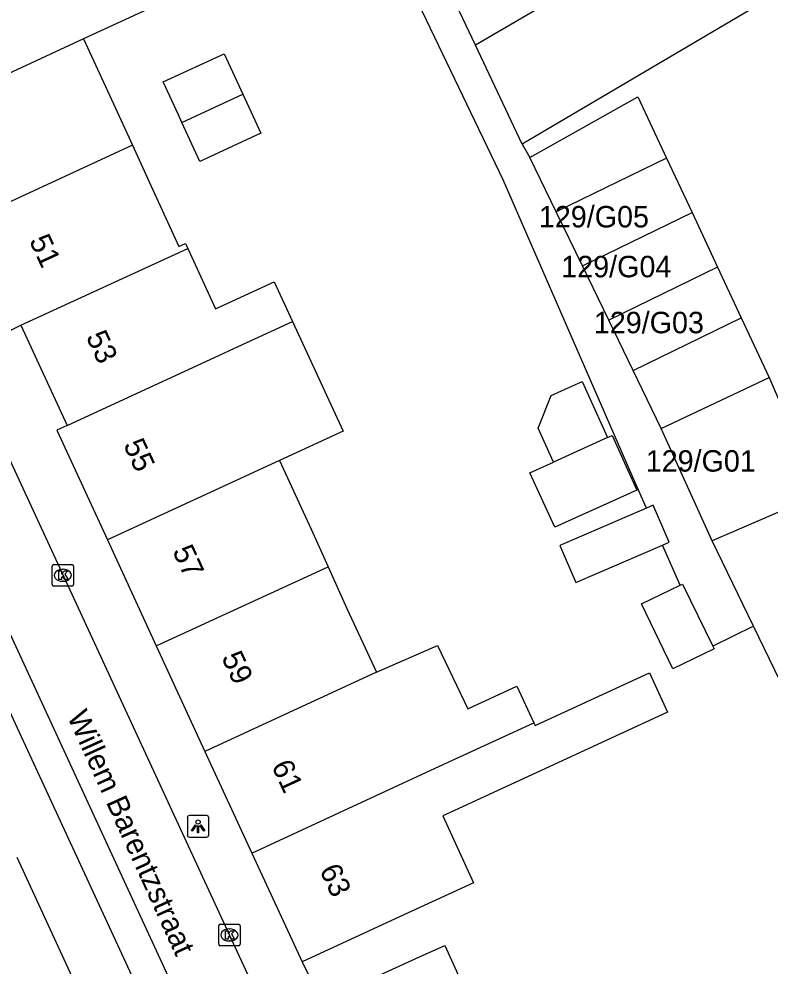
# Model space of a CAD drawing. Extents: x 160379 to 161131, y 383940 to 384849.
# Drawn here: x 161005.91 to 161040.91, y 384363.89 to 384408.04 of the extents above; entities that cross this region are included whole.
import ezdxf

# ---------------------------------------------------------------- set-up
doc = ezdxf.new("R2010")
doc.units = 0
for name, color, linetype in [('IMGEO_Kolk', 7, 'Continuous'), ('IMGEO_Lichtpunt', 7, 'Continuous'), ('IMGEO_Openbare_ruimte_label', 7, 'Continuous'), ('IMGEO_Pand', 7, 'Continuous'), ('IMGEO_Pand_nummerreeks', 7, 'Continuous'), ('IMGEO_Rijbaan_lokaal_open', 7, 'Continuous'), ('IMGEO_Voetpad_open', 7, 'Continuous')]:
    doc.layers.add(name, color=color, linetype=linetype)

msp = doc.modelspace()

# ---------------------------------------------------------------- linework, layer by layer
at = {"layer": 'IMGEO_Kolk'}
for p, q in [((161007.453, 384381.681), (161007.453, 384382.533)), ((161007.528, 384382.607), (161008.38, 384382.607)), ((161008.454, 384382.533), (161008.454, 384381.681)), ((161007.941, 384382.387), (161007.966, 384382.387)), ((161008.38, 384381.607), (161007.528, 384381.607)), ((161007.964, 384381.827), (161007.939, 384381.827)), ((161015.217, 384364.916), (161015.217, 384365.768)), ((161015.292, 384365.842), (161016.144, 384365.842)), ((161016.218, 384365.768), (161016.218, 384364.916)), ((161015.705, 384365.622), (161015.73, 384365.622)), ((161016.144, 384364.842), (161015.292, 384364.842)), ((161015.728, 384365.062), (161015.703, 384365.062))]:
    msp.add_line(p, q, dxfattribs=at)
for points in [[(161007.453, 384381.681), (161007.453, 384382.533)], [(161007.528, 384382.607), (161008.38, 384382.607)], [(161008.454, 384382.533), (161008.454, 384381.681)], [(161007.774, 384382.307), (161007.897, 384382.307), (161007.897, 384382.156), (161008.027, 384382.307), (161008.191, 384382.307), (161008.045, 384382.156), (161008.198, 384381.907), (161008.046, 384381.907), (161007.961, 384382.071), (161007.897, 384382.004), (161007.897, 384381.907), (161007.774, 384381.907), (161007.774, 384382.307)], [(161008.38, 384381.607), (161007.528, 384381.607)], [(161015.217, 384364.916), (161015.217, 384365.768)], [(161015.292, 384365.842), (161016.144, 384365.842)], [(161016.218, 384365.768), (161016.218, 384364.916)], [(161015.538, 384365.542), (161015.661, 384365.542), (161015.661, 384365.391), (161015.791, 384365.542), (161015.955, 384365.542), (161015.809, 384365.391), (161015.962, 384365.142), (161015.81, 384365.142), (161015.725, 384365.306), (161015.661, 384365.239), (161015.661, 384365.142), (161015.538, 384365.142), (161015.538, 384365.542)], [(161016.144, 384364.842), (161015.292, 384364.842)]]:
    msp.add_lwpolyline(points, dxfattribs=at)
for centre, start, end in [((161007.53, 384382.531), 91.552, 178.448), ((161007.53, 384382.531), 91.552, 178.448), ((161008.378, 384382.531), 1.552, 88.448), ((161008.378, 384382.531), 1.552, 88.448), ((161007.53, 384381.683), 181.552, 268.448), ((161007.53, 384381.683), 181.552, 268.448), ((161008.378, 384381.683), 271.552, 358.448), ((161008.378, 384381.683), 271.552, 358.448), ((161015.294, 384365.766), 91.552, 178.448), ((161015.294, 384365.766), 91.552, 178.448), ((161016.142, 384365.766), 1.552, 88.448), ((161016.142, 384365.766), 1.552, 88.448), ((161015.294, 384364.918), 181.552, 268.448), ((161015.294, 384364.918), 181.552, 268.448), ((161016.142, 384364.918), 271.552, 358.448), ((161016.142, 384364.918), 271.552, 358.448)]:
    msp.add_arc(centre, 0.0765, start, end, dxfattribs=at)
for centre, major_axis, ratio, start_param, end_param in [((161007.94, 384382.107), (-0.387, 0.002), 0.722429, 4.712389, 7.853982), ((161007.965, 384382.107), (-0.39, 0.002), 0.717154, 1.570796, 4.712389), ((161015.704, 384365.342), (-0.387, 0.002), 0.722429, 4.712389, 7.853982), ((161015.729, 384365.342), (-0.39, 0.002), 0.717154, 1.570796, 4.712389)]:
    msp.add_ellipse(centre, major_axis=major_axis, ratio=ratio, start_param=start_param, end_param=end_param, dxfattribs=at)
at = {"layer": 'IMGEO_Lichtpunt'}
for p, q in [((161013.757, 384370.809), (161013.757, 384370.002)), ((161013.757, 384370.809), (161013.757, 384370.002)), ((161014.659, 384370.904), (161013.851, 384370.904)), ((161014.659, 384370.904), (161013.851, 384370.904)), ((161014.753, 384370.002), (161014.753, 384370.809)), ((161014.753, 384370.002), (161014.753, 384370.809)), ((161013.851, 384369.908), (161014.659, 384369.908)), ((161013.851, 384369.908), (161014.659, 384369.908))]:
    msp.add_line(p, q, dxfattribs=at)
for points in [[(161014.131, 384370.473), (161014.17, 384370.445), (161013.982, 384370.183), (161013.944, 384370.21), (161014.131, 384370.473)], [(161014.233, 384370.425), (161014.28, 384370.425), (161014.28, 384370.103), (161014.233, 384370.103), (161014.233, 384370.425)], [(161014.343, 384370.445), (161014.381, 384370.472), (161014.568, 384370.21), (161014.529, 384370.182), (161014.343, 384370.445)]]:
    msp.add_lwpolyline(points, dxfattribs=at)
msp.add_circle((161014.256, 384370.607), 0.0994, dxfattribs=at)
for centre, start, end in [((161013.851, 384370.809), 90, 180), ((161013.851, 384370.809), 90, 180), ((161014.659, 384370.809), 0, 90), ((161014.659, 384370.809), 0, 90), ((161013.851, 384370.002), 180, 270), ((161013.851, 384370.002), 180, 270), ((161014.659, 384370.002), 270, 0), ((161014.659, 384370.002), 270, 360)]:
    msp.add_arc(centre, 0.0946, start, end, dxfattribs=at)
at = {"layer": 'IMGEO_Pand'}
for points in [[(161011.796, 384414.438), (161012.546, 384414.784), (161013.413, 384412.908), (161010.813, 384411.707), (161012.232, 384408.634), (161008.922, 384407.105)], [(161040.15, 384411.391), (161039.847, 384411.212), (161038.535, 384413.455), (161027.184, 384406.816)], [(161027.184, 384406.816), (161024.948, 384411.546)], [(161040.15, 384411.391), (161041.385, 384409.298), (161029.363, 384402.205)], [(161008.922, 384407.105), (161000.944, 384403.42)], [(161008.922, 384407.105), (161010.314, 384404.087), (161011.198, 384402.153)], [(161029.363, 384402.205), (161027.184, 384406.816)], [(161013.503, 384403.217), (161013.344, 384403.562), (161012.632, 384405.105), (161015.476, 384406.417), (161016.347, 384404.531)], [(161016.347, 384404.531), (161017.187, 384402.71), (161014.343, 384401.398), (161013.503, 384403.217)], [(161013.503, 384403.217), (161016.347, 384404.531)], [(161029.72, 384401.578), (161034.757, 384404.414), (161036.094, 384401.552)], [(161011.198, 384402.153), (161003.237, 384398.475)], [(161011.198, 384402.153), (161012.058, 384400.271), (161013.365, 384397.436), (161013.669, 384397.577), (161013.779, 384397.338)], [(161030.945, 384399.053), (161029.72, 384401.578)], [(161036.094, 384401.552), (161030.945, 384399.053)], [(161036.094, 384401.552), (161037.282, 384399.009)], [(161032.17, 384396.529), (161030.945, 384399.053)], [(161032.17, 384396.529), (161037.282, 384399.009)], [(161037.282, 384399.009), (161038.47, 384396.467)], [(161003.237, 384398.475), (161005.529, 384393.53), (161005.996, 384393.765)], [(161005.996, 384393.765), (161013.779, 384397.338)], [(161013.779, 384397.338), (161015.076, 384394.527), (161017.807, 384395.788), (161018.661, 384393.94)], [(161033.395, 384394.004), (161032.17, 384396.529)], [(161038.47, 384396.467), (161033.395, 384394.004)], [(161038.47, 384396.467), (161039.574, 384394.105)], [(161008.154, 384389.085), (161015.254, 384392.366), (161015.929, 384392.678), (161018.661, 384393.94)], [(161018.661, 384393.94), (161021.021, 384388.832), (161018.048, 384387.458)], [(161034.532, 384391.659), (161033.395, 384394.004)], [(161034.532, 384391.659), (161039.574, 384394.105)], [(161039.574, 384394.105), (161040.872, 384391.326)], [(161005.996, 384393.765), (161008.154, 384389.085)], [(161035.844, 384388.955), (161034.532, 384391.659)], [(161035.844, 384388.955), (161040.872, 384391.326)], [(161040.872, 384391.326), (161043.221, 384385.874)], [(161030.82, 384387.382), (161030.104, 384388.963), (161030.717, 384390.484), (161032.152, 384391.134), (161033.336, 384388.522)], [(161008.154, 384389.085), (161007.674, 384388.864), (161010.031, 384383.754)], [(161038.217, 384383.719), (161035.844, 384388.955)], [(161033.336, 384388.522), (161033.557, 384388.622), (161034.709, 384386.079), (161030.878, 384384.343), (161029.725, 384386.886), (161030.82, 384387.382)], [(161033.336, 384388.522), (161030.82, 384387.382)], [(161018.048, 384387.458), (161010.031, 384383.754)], [(161018.048, 384387.458), (161019.528, 384384.249), (161020.315, 384382.507)], [(161043.221, 384385.874), (161038.217, 384383.719)], [(161043.221, 384385.874), (161045.337, 384381.239), (161047.188, 384376.609), (161045.203, 384375.981), (161042.392, 384375.092), (161040.147, 384379.73)], [(161035.154, 384385.234), (161031.118, 384383.496), (161031.86, 384381.773), (161035.906, 384383.515)], [(161035.906, 384383.515), (161036.207, 384383.645), (161035.465, 384385.368), (161035.154, 384385.234)], [(161010.031, 384383.754), (161012.311, 384378.811)], [(161040.147, 384379.73), (161038.217, 384383.719)], [(161012.311, 384378.811), (161020.315, 384382.507)], [(161020.315, 384382.507), (161021.192, 384380.565), (161022.572, 384377.594)], [(161038.24, 384378.807), (161038.305, 384378.673), (161036.381, 384377.742), (161034.916, 384380.769), (161036.723, 384381.644)], [(161036.723, 384381.644), (161036.839, 384381.7), (161038.24, 384378.807)], [(161012.311, 384378.811), (161014.576, 384373.9)], [(161022.572, 384377.594), (161025.422, 384378.839), (161026.822, 384375.881), (161029.12, 384376.943), (161029.911, 384375.233)], [(161022.572, 384377.594), (161014.576, 384373.9)], [(161029.911, 384375.233), (161029.973, 384375.098), (161035.289, 384377.554), (161036.133, 384375.728), (161030.817, 384373.272), (161026.215, 384371.146), (161025.661, 384370.89), (161027.096, 384367.777), (161023.642, 384366.184), (161019.101, 384364.089)], [(161016.762, 384369.16), (161025.309, 384373.109), (161029.911, 384375.233)], [(161014.576, 384373.9), (161016.762, 384369.16)], [(161009.208, 384361.599), (161005.822, 384368.948)], [(161016.762, 384369.16), (161019.101, 384364.089)], [(161020.02, 384362.242), (161024.57, 384364.316), (161025.754, 384364.855), (161027.159, 384361.772)]]:
    msp.add_lwpolyline(points, dxfattribs=at)
at = {"layer": 'IMGEO_Rijbaan_lokaal_open'}
for points in [[(161004.279, 384390.07), (161016.657, 384363.318)], [(161023.221, 384341.065), (161021.739, 384344.199), (161001.198, 384388.663)]]:
    msp.add_lwpolyline(points, dxfattribs=at)
at = {"layer": 'IMGEO_Voetpad_open'}
for points in [[(161035.154, 384385.234), (161034.615, 384386.469), (161029.307, 384398.62), (161028.47, 384400.535), (161019.655, 384418.936), (161015.953, 384422.487), (161004.798, 384442.903)], [(161029.363, 384402.205), (161029.72, 384401.578)], [(160999.793, 384388.02), (161000, 384387.572), (161013.731, 384357.89)], [(161036.723, 384381.644), (161035.906, 384383.515)], [(161040.147, 384379.73), (161038.24, 384378.807)], [(161019.101, 384364.089), (161020.02, 384362.242)]]:
    msp.add_lwpolyline(points, dxfattribs=at)

# ---------------------------------------------------------------- texts
at = {"layer": 'IMGEO_Openbare_ruimte_label'}
msp.add_text('Willem Barentzstraat', height=1, rotation=294.3871, dxfattribs=at).set_placement((161008.141, 384375.532))
at = {"layer": 'IMGEO_Pand_nummerreeks'}
for s, p in [('129/G05', (161030.14, 384398.321)), ('129/G04', (161031.183, 384395.997)), ('129/G03', (161032.701, 384393.388)), ('129/G01', (161035.12, 384386.937))]:
    msp.add_text(s, height=1, dxfattribs=at).set_placement(p)
for s, rotation, p in [('51', 294.8719, (161006.369, 384397.71)), ('53', 294.7573, (161009.017, 384393.231)), ('55', 294.763, (161010.759, 384388.192)), ('57', 294.763, (161013.044, 384383.237)), ('59', 294.763, (161015.33, 384378.282)), ('61', 294.763, (161017.662, 384373.225)), ('63', 294.763, (161019.901, 384368.372))]:
    msp.add_text(s, height=1, rotation=rotation, dxfattribs=at).set_placement(p)

doc.saveas('drawing.dxf')
